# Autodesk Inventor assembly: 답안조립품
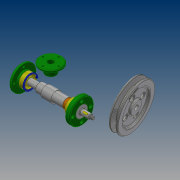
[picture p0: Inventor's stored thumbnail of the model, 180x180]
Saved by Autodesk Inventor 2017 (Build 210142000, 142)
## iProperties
Part Number: 답안조립품
Material: 일반
Document SubType Name: Assembly
Designer: 19
Author: 19
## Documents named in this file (15)
- C:\Users\19\Desktop\480414V1005\답안조립품.iam
- C:\Users\19\Desktop\480414V1005\본체.ipt
- C:\Users\19\Desktop\480414V1005\뒤커버.ipt
- C:\Users\19\Desktop\480414V1005\상부커버.ipt
- C:\Users\19\Desktop\480414V1005\앞커버.ipt
- C:\Users\19\Desktop\480414V1005\베어링 6202.ipt
- 베어링 6202.ipt
- C:\Users\19\Desktop\480414V1005\편심축.ipt
- C:\Users\19\Desktop\480414V1005\멈춤링 15x1.ipt
- C:\Users\19\Desktop\480414V1005\부시.ipt
- C:\Users\19\Desktop\480414V1005\키 4x4x12.ipt
- C:\Users\19\Desktop\480414V1005\멈춤링 35x1.6.ipt
- 멈춤링 35x1.6.ipt
- C:\Users\19\Desktop\480414V1005\오일 실 15 30 7.ipt
- C:\Users\19\Desktop\480414V1005\V-벨트풀리.ipt
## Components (1 placed, 1 different names)
1. V-벨트풀리:1
